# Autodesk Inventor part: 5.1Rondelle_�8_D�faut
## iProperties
Created: 2011-01
Part Number: 5.1Rondelle_�8_D�faut
Document SubType Name: Modeling
Designer: eric
Density: 1 g/cm^3
Mass: 0.298577 g
Surface Area: 5.2251 cm^2
Volume: 0.298577 cm^3
Author: eric
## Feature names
1. Base1
